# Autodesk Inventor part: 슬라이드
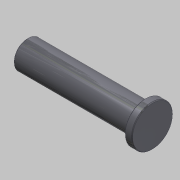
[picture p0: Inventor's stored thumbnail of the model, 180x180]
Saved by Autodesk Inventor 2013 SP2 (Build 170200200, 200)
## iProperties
Created: 2015-10
Part Number: 슬라이드
Document SubType Name: Modeling
Designer: mdu
Density: 7.86 g/cm^3
Material: 강철, 연강
Mass: 1589.24 g
Surface Area: 264.883 cm^2
Volume: 202.193 cm^3
Author: mdu
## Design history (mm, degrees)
sketch "스케치1"
  geometry: L1 (-75, 162)-(-75, 58) reference; L2 (-148, 110)-(22, 110); L3 (-148, 110)-(-148, 129); L4 (-148, 129)-(12, 129); L5 (12, 129)-(12, 138); L6 (12, 138)-(22, 138); L7 (22, 138)-(22, 110); 2 further points
  constraints: 12 end point, 3 parallel, 3 perpendicular, 1 midpoint, 1 point on line
  dimensions: "d0" = 56 diameter of L6 L2; "d1" = 38 diameter of L4 L2; "d2" = 10 distance of L5.end L6.end; "d3" = 170 distance of L2.start L2.end; "d4" = 73 distance between parallel lines of L3 L1
revolve "회전1" sketch "스케치1" stored, may be unused: angle "d5" = 90 deg
hole "구멍1" diameter "d11" = 13.376; stored, may be unused: countersink angle "d15" = 90 deg, drill point angle "d17" = 118 deg; dims "d9" = 10, "d10" = 10, "d12" = 22, "d13" = 4, "d14" = 2, "d16" = 25
chamfer "모따기1" distance "d6" = 1; stored, may be unused: second distance "d7" = 2, angle "d8" = 45 deg
node "솔리드1"
node "참조1"
